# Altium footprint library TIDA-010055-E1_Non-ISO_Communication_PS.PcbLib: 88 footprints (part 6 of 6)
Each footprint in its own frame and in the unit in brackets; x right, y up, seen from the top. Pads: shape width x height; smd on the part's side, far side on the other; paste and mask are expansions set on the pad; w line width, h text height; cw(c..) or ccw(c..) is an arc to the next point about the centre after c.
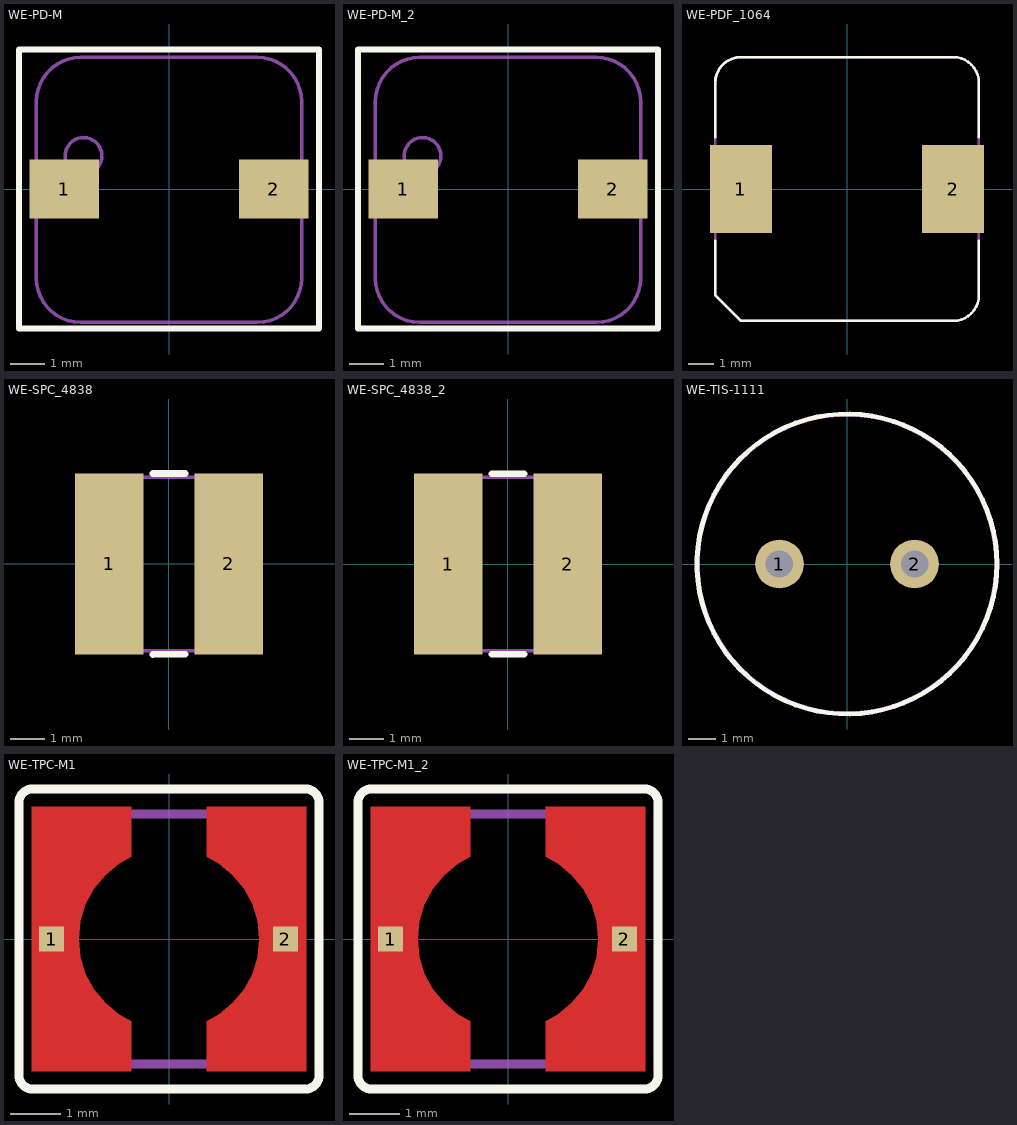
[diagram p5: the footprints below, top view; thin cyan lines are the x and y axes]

## WE-PD-M [mm] "Wurth Elektronik recommended land pattern, 2008-01-04"
height 4.5
pads (2):
  rect 2x1.7 smd: 1(-3,0) 2(3,0)
Top Overlay:
  lines w0.178: -4.3,-4 0,-4 4.3,-4 4.3,0 4.3,4 0,4 -4.3,4 -4.3,0 -4.3,-4
Mechanical 5:
  circle w0.102: c-2.45,0.95 r0.525
  lines w0.102: -3.8,-2.555 ccw(c-2.53,-2.555) -2.53,-3.825 2.53,-3.825 ccw(c2.53,-2.555) 3.8,-2.555 3.8,2.505 ccw(c2.53,2.505) 2.53,3.775 -2.53,3.775 ccw(c-2.53,2.505) -3.8,2.505 -3.8,-2.555
  text ".Designator" at 0.607,-0.813 h0.64
3D body: height 4.5, standoff 0, extent -3.799,-3.824 3.799,3.774
3D body: height 4.5, standoff 4.4, extent -2.974,0.426 -1.926,1.474

## WE-PD-M_2 [mm]
pads (2):
  rect 2x1.7 smd: 1(-3,0) 2(3,0)
Top Overlay:
  lines w0.178: -4.3,-4 0,-4 4.3,-4 4.3,0 4.3,4 0,4 -4.3,4 -4.3,0 -4.3,-4
Mechanical 5:
  circle w0.102: c-2.45,0.95 r0.525
  lines w0.102: -3.8,-2.555 ccw(c-2.53,-2.555) -2.53,-3.825 2.53,-3.825 ccw(c2.53,-2.555) 3.8,-2.555 3.8,2.505 ccw(c2.53,2.505) 2.53,3.775 -2.53,3.775 ccw(c-2.53,2.505) -3.8,2.505 -3.8,-2.555
  text ".Designator" at -0.102,0.787 h0.64
3D body: height 4.5, standoff 0, extent -3.799,-3.824 3.799,3.774
3D body: height 4.5, standoff 4.4, extent -2.974,0.426 -1.926,1.474

## WE-PDF_1064 [mm] "WERTH"
height 6.4
pads (2):
  rect 2.4x3.4 smd: 1(-4.1,0) 2(4.1,0)
Top Overlay:
  lines w0.1: -5.1,-2 -5.1,-4.1 -4.1,-5.1 3.7,-5.1 4.1,-5.1 ccw(c4.1,-4.1) 5.1,-4.1 5.1,-4 5.1,-2 ; -5.1,2 -5.1,4.1 cw(c-4.1,4.1) -4.1,5.1 4.1,5.1 cw(c4.1,4.1) 5.1,4.1 5.1,2
Mechanical 5:
  lines w0.1: -5.1,-4.1 -5.1,4.1 cw(c-4.1,4.1) -4.1,5.1 4.1,5.1 cw(c4.1,4.1) 5.1,4.1 5.1,-4.1 cw(c4.1,-4.1) 4.1,-5.1 -4.1,-5.1 -5.1,-4.1
  text ".Designator" at -0.086,0.94 h0.64
3D body "WE-PDF_1064.stp": height 6.35, standoff -0.05, extent -5.1,-5.1 5.1,5.1

## WE-SPC_4838 [mm] "WURTH"
height 4.1
pads (2):
  rect 2x5.3 smd: 1(-1.75,0) 2(1.75,0)
Top Overlay:
  lines w0.2: -0.475,-2.65 0.475,-2.65 ; -0.475,2.65 0.475,2.65
Mechanical 5:
  lines w0.1: -2.55,-2.55 -2.55,2.55 2.55,2.55 2.55,-2.55 -2.55,-2.55
  text ".Designator" at 0.559,-0.991 h0.64
3D body: height 4.1, standoff 0, extent -2.549,-2.549 2.549,2.549

## WE-SPC_4838_2 [mm]
pads (2):
  rect 2x5.3 smd: 1(-1.75,0) 2(1.75,0)
Top Overlay:
  lines w0.2: -0.475,-2.65 0.475,-2.65 ; -0.475,2.65 0.475,2.65
Mechanical 5:
  lines w0.1: -2.55,-2.55 -2.55,2.55 2.55,2.55 2.55,-2.55 -2.55,-2.55
  text ".Designator" at 0.296,-0.513 h0.64
3D body: height 4.1, standoff 0, extent -2.549,-2.549 2.549,2.549

## WE-TIS-1111 [mm] "WURTH"
height 11.5
pads (2):
  round 1.8 hole 1.016: 1(-2.5,0) 2(2.5,0)
Top Overlay:
  circle w0.18: c0,0 r5.55
Mechanical 5:
  circle w0.1: c0,0 r5.5
  text ".Designator" at -0.012,-0.581 h0.64
3D body: height 2, standoff -2, extent 2.178,-0.324 2.825,0.324
3D body: height 2, standoff -2, extent -2.822,-0.324 -2.175,0.324
3D body: height 11.5, standoff 0, extent -5.499,-5.499 5.499,5.499

## WE-TPC-M1 [mm] "Wurth Elektronik recommended land pattern"
height 2
pads (2):
  rect 0.5x0.5 smd: 1(-2.35,0) 2(2.325,0)
Top Layer:
  region: 0.75,1.64 1.005,1.504 1.279,1.279 1.504,1.005 1.671,0.692 1.774,0.353 1.809,0 1.774,-0.353 1.671,-0.692 1.504,-1.005 1.279,-1.279 1.005,-1.504 0.75,-1.64 0.75,-2.65 2.75,-2.65 2.75,2.65 0.75,2.65
  region: -0.75,1.64 -1.005,1.504 -1.279,1.279 -1.504,1.005 -1.671,0.692 -1.774,0.353 -1.809,0 -1.774,-0.353 -1.671,-0.692 -1.504,-1.005 -1.279,-1.279 -1.005,-1.504 -0.75,-1.64 -0.75,-2.65 -2.75,-2.65 -2.75,2.65 -0.75,2.65
Top Overlay:
  lines w0.178: -2.73,-3 ccw(c-2.73,-3) -2.73,-3 ; -2.73,-3 cw(c-2.73,-2.73) -3,-2.73 -3,-1.73 -3,0 -3,1.73 -3,2.73 cw(c-2.73,2.73) -2.73,3 ; -2.73,-3 -1.73,-3 0,-3 1.73,-3 2.73,-3 ; -2.73,3 ccw(c-2.73,3) -2.73,3 ; -2.73,3 -1.73,3 0,3 1.73,3 2.73,3 ; 2.73,-3 ccw(c2.73,-2.73) 3,-2.73 3,-1.73 3,0 3,1.73 3,2.73 ccw(c2.73,2.73) 2.73,3 ; 2.73,-3 ccw(c2.73,-3) 2.73,-3 ; 2.73,3 ccw(c2.73,3) 2.73,3
Top Paste:
  region: 0.75,1.64 1.005,1.504 1.279,1.279 1.504,1.005 1.671,0.692 1.774,0.353 1.809,0 1.774,-0.353 1.671,-0.692 1.504,-1.005 1.279,-1.279 1.005,-1.504 0.75,-1.64 0.75,-2.65 2.75,-2.65 2.75,2.65 0.75,2.65
  region: -0.75,1.64 -1.005,1.504 -1.279,1.279 -1.504,1.005 -1.671,0.692 -1.774,0.353 -1.809,0 -1.774,-0.353 -1.671,-0.692 -1.504,-1.005 -1.279,-1.279 -1.005,-1.504 -0.75,-1.64 -0.75,-2.65 -2.75,-2.65 -2.75,2.65 -0.75,2.65
Top Solder:
  region: -0.75,1.64 -1.005,1.504 -1.279,1.279 -1.504,1.005 -1.671,0.692 -1.774,0.353 -1.809,0 -1.774,-0.353 -1.671,-0.692 -1.504,-1.005 -1.279,-1.279 -1.005,-1.504 -0.75,-1.64 -0.75,-2.65 -2.75,-2.65 -2.75,2.65 -0.75,2.65
  region: 0.75,1.64 1.005,1.504 1.279,1.279 1.504,1.005 1.671,0.692 1.774,0.353 1.809,0 1.774,-0.353 1.671,-0.692 1.504,-1.005 1.279,-1.279 1.005,-1.504 0.75,-1.64 0.75,-2.65 2.75,-2.65 2.75,2.65 0.75,2.65
Mechanical 5:
  lines w0.102: -2.54,-2.54 2.54,-2.54 2.54,2.54 -2.54,2.54 -2.54,-2.54
  text ".Designator" at -0.218,0.538 h0.64
Mechanical 13:
  lines w0.178: -2.5,-1.23 ccw(c-1.23,-1.23) -1.23,-2.5 1.23,-2.5 ccw(c1.23,-1.23) 2.5,-1.23 2.5,1.23 ccw(c1.23,1.23) 1.23,2.5 -1.23,2.5 ccw(c-1.23,1.23) -2.5,1.23 -2.5,-1.23
3D body: height 2, standoff 0, extent -2.499,-2.499 2.499,2.499

## WE-TPC-M1_2 [mm]
pads (2):
  rect 0.5x0.5 smd: 1(-2.35,0) 2(2.325,0)
Top Layer:
  region: 0.75,1.64 1.005,1.504 1.279,1.279 1.504,1.005 1.671,0.692 1.774,0.353 1.809,0 1.774,-0.353 1.671,-0.692 1.504,-1.005 1.279,-1.279 1.005,-1.504 0.75,-1.64 0.75,-2.65 2.75,-2.65 2.75,2.65 0.75,2.65
  region: -0.75,1.64 -1.005,1.504 -1.279,1.279 -1.504,1.005 -1.671,0.692 -1.774,0.353 -1.809,0 -1.774,-0.353 -1.671,-0.692 -1.504,-1.005 -1.279,-1.279 -1.005,-1.504 -0.75,-1.64 -0.75,-2.65 -2.75,-2.65 -2.75,2.65 -0.75,2.65
Top Overlay:
  lines w0.178: -2.73,-3 ccw(c-2.73,-3) -2.73,-3 ; -2.73,-3 cw(c-2.73,-2.73) -3,-2.73 -3,-1.73 -3,0 -3,1.73 -3,2.73 cw(c-2.73,2.73) -2.73,3 ; -2.73,-3 -1.73,-3 0,-3 1.73,-3 2.73,-3 ; -2.73,3 ccw(c-2.73,3) -2.73,3 ; -2.73,3 -1.73,3 0,3 1.73,3 2.73,3 ; 2.73,-3 ccw(c2.73,-2.73) 3,-2.73 3,-1.73 3,0 3,1.73 3,2.73 ccw(c2.73,2.73) 2.73,3 ; 2.73,-3 ccw(c2.73,-3) 2.73,-3 ; 2.73,3 ccw(c2.73,3) 2.73,3
Top Paste:
  region: 0.75,1.64 1.005,1.504 1.279,1.279 1.504,1.005 1.671,0.692 1.774,0.353 1.809,0 1.774,-0.353 1.671,-0.692 1.504,-1.005 1.279,-1.279 1.005,-1.504 0.75,-1.64 0.75,-2.65 2.75,-2.65 2.75,2.65 0.75,2.65
  region: -0.75,1.64 -1.005,1.504 -1.279,1.279 -1.504,1.005 -1.671,0.692 -1.774,0.353 -1.809,0 -1.774,-0.353 -1.671,-0.692 -1.504,-1.005 -1.279,-1.279 -1.005,-1.504 -0.75,-1.64 -0.75,-2.65 -2.75,-2.65 -2.75,2.65 -0.75,2.65
Top Solder:
  region: -0.75,1.64 -1.005,1.504 -1.279,1.279 -1.504,1.005 -1.671,0.692 -1.774,0.353 -1.809,0 -1.774,-0.353 -1.671,-0.692 -1.504,-1.005 -1.279,-1.279 -1.005,-1.504 -0.75,-1.64 -0.75,-2.65 -2.75,-2.65 -2.75,2.65 -0.75,2.65
  region: 0.75,1.64 1.005,1.504 1.279,1.279 1.504,1.005 1.671,0.692 1.774,0.353 1.809,0 1.774,-0.353 1.671,-0.692 1.504,-1.005 1.279,-1.279 1.005,-1.504 0.75,-1.64 0.75,-2.65 2.75,-2.65 2.75,2.65 0.75,2.65
Mechanical 5:
  lines w0.102: -2.54,-2.54 2.54,-2.54 2.54,2.54 -2.54,2.54 -2.54,-2.54
  text ".Designator" at -0.238,0.218 h0.64
Mechanical 13:
  lines w0.178: -2.5,-1.23 ccw(c-1.23,-1.23) -1.23,-2.5 1.23,-2.5 ccw(c1.23,-1.23) 2.5,-1.23 2.5,1.23 ccw(c1.23,1.23) 1.23,2.5 -1.23,2.5 ccw(c-1.23,1.23) -2.5,1.23 -2.5,-1.23
3D body: height 2, standoff 0, extent -2.499,-2.499 2.499,2.499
